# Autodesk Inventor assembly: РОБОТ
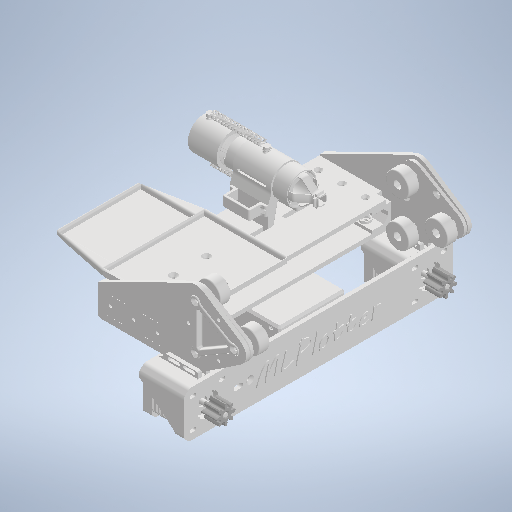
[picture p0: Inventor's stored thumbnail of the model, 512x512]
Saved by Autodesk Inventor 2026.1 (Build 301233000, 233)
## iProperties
Created: 2025-12
Part Number: РОБОТ
Document SubType Name: Assembly
Designer: Yury Melnikov
Author: Yury Melnikov
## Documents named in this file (8)
- C:\Users\user\Documents\Проекты\ВсОШ_РОБО\Робот\РОБОТ.iam
- C:\Users\user\Documents\Проекты\ВсОШ_РОБО\Робот\Направляющие.ipt
- C:\Users\user\Documents\Проекты\ВсОШ_РОБО\Робот\Твердое тело1.ipt
- C:\Users\user\Documents\Проекты\ВсОШ_РОБО\Робот\Твердое тело3.ipt
- C:\Users\user\Documents\Проекты\ВсОШ_РОБО\Робот\Твердое тело4.ipt
- C:\Users\user\Documents\Проекты\ВсОШ_РОБО\Робот\Шестеренки\Шестеренка.ipt
- C:\Users\user\Documents\Проекты\ВсОШ_РОБО\Робот\МАРКЕР.ipt
- C:\Users\user\Documents\Проекты\ВсОШ_РОБО\Робот\аККУМ.ipt
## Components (10 placed, 7 different names)
1. Направляющие:1
2. Твердое тело1:1
3. Твердое тело3:1 — Совмещение:1, Совмещение:2, Совмещение:3, Совмещение:4, Угол:1, Совмещение:17, Симметрия:4
4. Твердое тело4:1 — Совмещение:13, Совмещение:14, Совмещение:15, Совмещение:17, Симметрия:2, Совмещение:26
5. Шестеренка:1 — Совмещение:6, Совмещение:7, Совмещение:8, Заподлицо:2
6. Твердое тело1:2
7. Твердое тело3:2 — Совмещение:13, Совмещение:16, Угол:3, Симметрия:4
8. Шестеренка:2 — Совмещение:19, Симметрия:2
9. МАРКЕР:1 — Совмещение:22, Совмещение:23, Совмещение:24
10. аККУМ:1 — Совмещение:25, Совмещение:26, Совмещение:27, Угол:6, Совмещение:28, Угол:7
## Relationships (27: Mate 20, Angle 4, Symmetry 2, Flush 1)
- Совмещение:1 [Mate]: Твердое тело3:1
- Совмещение:2 [Mate]: Твердое тело3:1
- Совмещение:3 [Mate]: Твердое тело3:1
- Совмещение:4 [Mate]: Твердое тело3:1
- Угол:1 [Angle]: Твердое тело3:1
- Совмещение:6 [Mate]: Шестеренка:1
- Совмещение:7 [Mate]: Шестеренка:1
- Совмещение:8 [Mate]: Шестеренка:1
- Заподлицо:2 [Flush]: Шестеренка:1
- Совмещение:13 [Mate]: Твердое тело4:1 ↔ Твердое тело3:2
- Совмещение:14 [Mate]: Твердое тело4:1
- Совмещение:15 [Mate]: Твердое тело4:1
- Совмещение:16 [Mate]: Твердое тело3:2
- Совмещение:17 [Mate]: Твердое тело3:1 ↔ Твердое тело4:1
- Угол:3 [Angle]: Твердое тело3:2
- Совмещение:19 [Mate]: Шестеренка:2
- Симметрия:2 [Symmetry]: Твердое тело4:1 ↔ Шестеренка:2
- Совмещение:22 [Mate]: МАРКЕР:1
- Совмещение:23 [Mate]: МАРКЕР:1
- Совмещение:24 [Mate]: МАРКЕР:1
- Совмещение:25 [Mate]: аККУМ:1
- Совмещение:26 [Mate]: Твердое тело4:1 ↔ аККУМ:1
- Совмещение:27 [Mate]: аККУМ:1
- Угол:6 [Angle]: аККУМ:1
- Совмещение:28 [Mate]: аККУМ:1
- Угол:7 [Angle]: аККУМ:1
- Симметрия:4 [Symmetry]: Твердое тело3:1 ↔ Твердое тело3:2
## Named parameters: d14_d2 = 0, d15_d3 = 0, d16_d9 = 0, d17_d13 = 0
